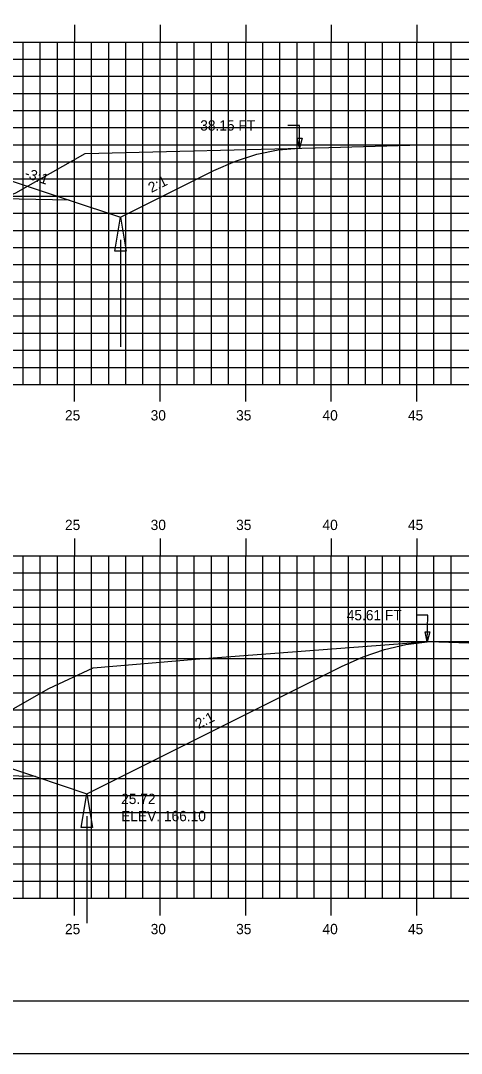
# Model space of a CAD drawing. Extents: x 1140759 to 1140929, y 608981 to 609091.
# Drawn here: x 1140863.9 to 1140889.6, y 608981.3 to 609041.6 of the extents above; entities that cross this region are included whole.
import ezdxf

# ---------------------------------------------------------------- set-up
doc = ezdxf.new("R2010")
doc.units = 0
for name, color, linetype in [('ANNOTATION', 7, 'Continuous'), ('BORDER', 7, 'Continuous'), ('D_Drainage_Ditch_Line', 7, 'Continuous'), ('D_Roadway_SlopeLines', 7, 'Continuous'), ('D_Roadway_SubGrade', 7, 'Continuous'), ('D_Text_Standard', 7, 'Continuous'), ('H_V ANNOTATION', 7, 'Continuous'), ('MAJOR', 7, 'Continuous'), ('MINOR', 7, 'Continuous'), ('PLOT BOUNDARY', 7, 'Continuous'), ('S_Roadway_Centerline', 7, 'Continuous')]:
    doc.layers.add(name, color=color, linetype=linetype)

msp = doc.modelspace()

# ---------------------------------------------------------------- linework, layer by layer
for points in [[(1140810.883, 609031.567), (1140812.133, 609031.496), (1140813.383, 609031.267), (1140814.633, 609030.879), (1140815.883, 609030.333), (1140816.276, 609030.136), (1140819.276, 609031.136), (1140827, 609033.711), (1140827.001, 609033.711), (1140831.001, 609033.871), (1140842.001, 609034.091), (1140853.001, 609033.871), (1140859.098, 609033.627), (1140866.688, 609031.097), (1140869.688, 609030.097), (1140875.149, 609032.828), (1140876.399, 609033.379), (1140877.649, 609033.781), (1140878.899, 609034.035), (1140880.149, 609034.141)], [(1140806.654, 608999.652), (1140807.904, 608999.725), (1140809.154, 608999.598), (1140810.404, 608999.272), (1140811.654, 608998.747), (1140816.276, 608996.435), (1140819.276, 608997.435), (1140827, 609000.01), (1140827.001, 609000.01), (1140831.001, 609000.17), (1140842.001, 609000.39), (1140853.001, 609000.17), (1140857.001, 609000.01), (1140864.725, 608997.435), (1140867.725, 608996.435), (1140882.606, 609003.876), (1140883.856, 609004.435), (1140885.106, 609004.861), (1140886.356, 609005.154), (1140887.606, 609005.314)]]:
    msp.add_lwpolyline(points)
at = {"layer": 'BORDER'}
msp.add_lwpolyline([(1140767.001, 608984.335), (1140927.001, 608984.335), (1140927.001, 609089.335), (1140767.001, 609089.335)], close=True, dxfattribs=at)
at = {"layer": 'D_Drainage_Ditch_Line'}
for p, q in [((1140869.688, 609028.785), (1140869.687, 609022.541)), ((1140867.725, 608995.123), (1140867.724, 608988.88))]:
    msp.add_line(p, q, dxfattribs=at)
for points in [[(1140870.016, 609028.128), (1140869.36, 609028.128), (1140869.688, 609030.097)], [(1140868.053, 608994.467), (1140867.396, 608994.467), (1140867.725, 608996.435)]]:
    msp.add_lwpolyline(points, close=True, dxfattribs=at)
at = {"layer": 'D_Roadway_SlopeLines'}
for points in [[(1140869.688, 609030.097), (1140875.149, 609032.828), (1140876.399, 609033.379), (1140877.649, 609033.781), (1140878.899, 609034.035), (1140880.149, 609034.141)], [(1140866.688, 609031.097), (1140869.688, 609030.097)], [(1140867.725, 608996.435), (1140882.606, 609003.876), (1140883.856, 609004.435), (1140885.106, 609004.861), (1140886.356, 609005.154), (1140887.606, 609005.314)], [(1140864.725, 608997.435), (1140867.725, 608996.435)]]:
    msp.add_lwpolyline(points, dxfattribs=at)
at = {"layer": 'D_Roadway_SubGrade'}
for points in [[(1140853.001, 609033.454), (1140853.001, 609033.621), (1140859.098, 609033.377), (1140859.098, 609033.627), (1140859.098, 609033.627), (1140866.688, 609031.097), (1140853.001, 609031.371)], [(1140853.001, 608999.753), (1140853.001, 608999.92), (1140857.001, 608999.76), (1140857.001, 609000.01), (1140857.001, 609000.01), (1140864.725, 608997.435), (1140853.001, 608997.67)]]:
    msp.add_lwpolyline(points, close=True, dxfattribs=at)
at = {"layer": 'D_Text_Standard'}
for points in [[(1140880.149, 609034.141), (1140880.149, 609035.465), (1140879.469, 609035.465)], [(1140887.606, 609005.304), (1140887.646, 609006.866), (1140886.966, 609006.866)]]:
    msp.add_lwpolyline(points, dxfattribs=at)
for points in [[(1140880.149, 609034.141), (1140880.004, 609034.723), (1140880.295, 609034.723)], [(1140887.606, 609005.304), (1140887.476, 609005.89), (1140887.767, 609005.882)]]:
    msp.add_lwpolyline(points, close=True, dxfattribs=at)
at = {"layer": 'MAJOR'}
for p, q in [((1140867.001, 609041.337), (1140867.001, 609040.335)), ((1140872.001, 609041.337), (1140872.001, 609040.335)), ((1140877.001, 609041.337), (1140877.001, 609040.335)), ((1140882.001, 609041.337), (1140882.001, 609040.335)), ((1140887.001, 609041.337), (1140887.001, 609040.335)), ((1140772.001, 609040.335), (1140912.001, 609040.335)), ((1140772.001, 609040.335), (1140912.001, 609040.335)), ((1140867.001, 609020.335), (1140867.001, 609040.335)), ((1140872.001, 609020.335), (1140872.001, 609040.335)), ((1140877.001, 609020.335), (1140877.001, 609040.335)), ((1140882.001, 609020.335), (1140882.001, 609040.335)), ((1140887.001, 609020.335), (1140887.001, 609040.335)), ((1140772.001, 609035.335), (1140912.001, 609035.335)), ((1140772.001, 609030.335), (1140912.001, 609030.335)), ((1140772.001, 609025.335), (1140912.001, 609025.335)), ((1140772.001, 609020.335), (1140912.001, 609020.335)), ((1140772.001, 609020.335), (1140912.001, 609020.335)), ((1140867.001, 609019.333), (1140867.001, 609020.335)), ((1140872.001, 609019.333), (1140872.001, 609020.335)), ((1140877.001, 609019.333), (1140877.001, 609020.335)), ((1140882.001, 609019.333), (1140882.001, 609020.335)), ((1140887.001, 609019.333), (1140887.001, 609020.335)), ((1140867.001, 609011.337), (1140867.001, 609010.335)), ((1140872.001, 609011.337), (1140872.001, 609010.335)), ((1140877.001, 609011.337), (1140877.001, 609010.335)), ((1140882.001, 609011.337), (1140882.001, 609010.335)), ((1140887.001, 609011.337), (1140887.001, 609010.335)), ((1140772.001, 609010.335), (1140912.001, 609010.335)), ((1140772.001, 609010.335), (1140912.001, 609010.335)), ((1140867.001, 608990.335), (1140867.001, 609010.335)), ((1140872.001, 608990.335), (1140872.001, 609010.335)), ((1140877.001, 608990.335), (1140877.001, 609010.335)), ((1140882.001, 608990.335), (1140882.001, 609010.335)), ((1140887.001, 608990.335), (1140887.001, 609010.335)), ((1140772.001, 609005.335), (1140912.001, 609005.335)), ((1140772.001, 609000.335), (1140912.001, 609000.335)), ((1140772.001, 608995.335), (1140912.001, 608995.335)), ((1140772.001, 608990.335), (1140912.001, 608990.335)), ((1140772.001, 608990.335), (1140912.001, 608990.335)), ((1140867.001, 608989.333), (1140867.001, 608990.335)), ((1140872.001, 608989.333), (1140872.001, 608990.335)), ((1140877.001, 608989.333), (1140877.001, 608990.335)), ((1140882.001, 608989.333), (1140882.001, 608990.335)), ((1140887.001, 608989.333), (1140887.001, 608990.335))]:
    msp.add_line(p, q, dxfattribs=at)
at = {"layer": 'MINOR'}
for p, q in [((1140864.001, 609020.335), (1140864.001, 609040.335)), ((1140865.001, 609020.335), (1140865.001, 609040.335)), ((1140866.001, 609020.335), (1140866.001, 609040.335)), ((1140868.001, 609020.335), (1140868.001, 609040.335)), ((1140869.001, 609020.335), (1140869.001, 609040.335)), ((1140870.001, 609020.335), (1140870.001, 609040.335)), ((1140871.001, 609020.335), (1140871.001, 609040.335)), ((1140873.001, 609020.335), (1140873.001, 609040.335)), ((1140874.001, 609020.335), (1140874.001, 609040.335)), ((1140875.001, 609020.335), (1140875.001, 609040.335)), ((1140876.001, 609020.335), (1140876.001, 609040.335)), ((1140878.001, 609020.335), (1140878.001, 609040.335)), ((1140879.001, 609020.335), (1140879.001, 609040.335)), ((1140880.001, 609020.335), (1140880.001, 609040.335)), ((1140881.001, 609020.335), (1140881.001, 609040.335)), ((1140883.001, 609020.335), (1140883.001, 609040.335)), ((1140884.001, 609020.335), (1140884.001, 609040.335)), ((1140885.001, 609020.335), (1140885.001, 609040.335)), ((1140886.001, 609020.335), (1140886.001, 609040.335)), ((1140888.001, 609020.335), (1140888.001, 609040.335)), ((1140889.001, 609020.335), (1140889.001, 609040.335)), ((1140772.001, 609039.335), (1140912.001, 609039.335)), ((1140772.001, 609038.335), (1140912.001, 609038.335)), ((1140772.001, 609037.335), (1140912.001, 609037.335)), ((1140772.001, 609036.335), (1140912.001, 609036.335)), ((1140772.001, 609034.335), (1140912.001, 609034.335)), ((1140772.001, 609033.335), (1140912.001, 609033.335)), ((1140772.001, 609032.335), (1140912.001, 609032.335)), ((1140772.001, 609031.335), (1140912.001, 609031.335)), ((1140772.001, 609029.335), (1140912.001, 609029.335)), ((1140772.001, 609028.335), (1140912.001, 609028.335)), ((1140772.001, 609027.335), (1140912.001, 609027.335)), ((1140772.001, 609026.335), (1140912.001, 609026.335)), ((1140772.001, 609024.335), (1140912.001, 609024.335)), ((1140772.001, 609023.335), (1140912.001, 609023.335)), ((1140772.001, 609022.335), (1140912.001, 609022.335)), ((1140772.001, 609021.335), (1140912.001, 609021.335)), ((1140864.001, 608990.335), (1140864.001, 609010.335)), ((1140865.001, 608990.335), (1140865.001, 609010.335)), ((1140866.001, 608990.335), (1140866.001, 609010.335)), ((1140868.001, 608990.335), (1140868.001, 609010.335)), ((1140869.001, 608990.335), (1140869.001, 609010.335)), ((1140870.001, 608990.335), (1140870.001, 609010.335)), ((1140871.001, 608990.335), (1140871.001, 609010.335)), ((1140873.001, 608990.335), (1140873.001, 609010.335)), ((1140874.001, 608990.335), (1140874.001, 609010.335)), ((1140875.001, 608990.335), (1140875.001, 609010.335)), ((1140876.001, 608990.335), (1140876.001, 609010.335)), ((1140878.001, 608990.335), (1140878.001, 609010.335)), ((1140879.001, 608990.335), (1140879.001, 609010.335)), ((1140880.001, 608990.335), (1140880.001, 609010.335)), ((1140881.001, 608990.335), (1140881.001, 609010.335)), ((1140883.001, 608990.335), (1140883.001, 609010.335)), ((1140884.001, 608990.335), (1140884.001, 609010.335)), ((1140885.001, 608990.335), (1140885.001, 609010.335)), ((1140886.001, 608990.335), (1140886.001, 609010.335)), ((1140888.001, 608990.335), (1140888.001, 609010.335)), ((1140889.001, 608990.335), (1140889.001, 609010.335)), ((1140772.001, 609009.335), (1140912.001, 609009.335)), ((1140772.001, 609008.335), (1140912.001, 609008.335)), ((1140772.001, 609007.335), (1140912.001, 609007.335)), ((1140772.001, 609006.335), (1140912.001, 609006.335)), ((1140772.001, 609004.335), (1140912.001, 609004.335)), ((1140772.001, 609003.335), (1140912.001, 609003.335)), ((1140772.001, 609002.335), (1140912.001, 609002.335)), ((1140772.001, 609001.335), (1140912.001, 609001.335)), ((1140772.001, 608999.335), (1140912.001, 608999.335)), ((1140772.001, 608998.335), (1140912.001, 608998.335)), ((1140772.001, 608997.335), (1140912.001, 608997.335)), ((1140772.001, 608996.335), (1140912.001, 608996.335)), ((1140772.001, 608994.335), (1140912.001, 608994.335)), ((1140772.001, 608993.335), (1140912.001, 608993.335)), ((1140772.001, 608992.335), (1140912.001, 608992.335)), ((1140772.001, 608991.335), (1140912.001, 608991.335))]:
    msp.add_line(p, q, dxfattribs=at)
at = {"layer": 'PLOT BOUNDARY'}
msp.add_lwpolyline([(1140758.908, 608981.276), (1140928.908, 608981.276), (1140928.908, 609091.276), (1140758.908, 609091.276)], close=True, dxfattribs=at)
at = {"layer": 'S_Roadway_Centerline'}
for points in [[(1140801.487, 609031.61), (1140807.51, 609031.545), (1140817.109, 609031.607), (1140818.751, 609031.199), (1140823.239, 609030.006), (1140825.606, 609030.431), (1140826.984, 609030.636), (1140828.295, 609030.749), (1140830.088, 609030.938), (1140836.661, 609031.15), (1140841.085, 609031.284), (1140845.133, 609031.054), (1140851.798, 609030.843), (1140853.505, 609030.727), (1140854.754, 609030.632), (1140856.271, 609030.176), (1140858.918, 609029.531), (1140863.578, 609031.533), (1140867.623, 609033.826), (1140881.853, 609034.183), (1140886.58, 609034.308), (1140902.941, 609034.493), (1140912.001, 609034.621)], [(1140801.751, 608998.976), (1140814.306, 609000.707), (1140815.787, 609000.705), (1140816.993, 609000.418), (1140823.481, 608999.018), (1140825.828, 608999.368), (1140826.874, 608999.635), (1140827.996, 608999.704), (1140830.23, 608999.898), (1140837.667, 609000.12), (1140841.075, 609000.147), (1140848.107, 608999.748), (1140851.527, 608999.693), (1140853.662, 608999.523), (1140854.647, 608999.437), (1140857.22, 608998.676), (1140858.176, 608998.42), (1140865.509, 609002.587), (1140868.086, 609003.78), (1140874.07, 609004.299), (1140887.7, 609005.321), (1140893.531, 609005.124), (1140897.997, 609004.657), (1140912.001, 609005.073)]]:
    msp.add_lwpolyline(points, dxfattribs=at)

# ---------------------------------------------------------------- texts
at = {"layer": 'ANNOTATION'}
for s, rotation, p in [('-3:1', 341.56522, (1140864.043, 609032.433)), ('2:1', 26.56505, (1140871.491, 609031.517)), ('2:1', 26.56505, (1140874.238, 609000.21))]:
    msp.add_text(s, height=0.6, rotation=rotation, dxfattribs=at).set_placement(p)
at = {"layer": 'D_Text_Standard'}
for s, p in [('38.15 FT', (1140874.346, 609035.165)), ('45.61 FT', (1140882.904, 609006.566)), ('25.72', (1140869.725, 608995.835)), ('ELEV. 166.10', (1140869.725, 608994.833))]:
    msp.add_text(s, height=0.6, dxfattribs=at).set_placement(p)
at = {"layer": 'H_V ANNOTATION'}
for s, p in [('25', (1140866.447, 609018.235)), ('30', (1140871.45, 609018.235)), ('35', (1140876.442, 609018.235)), ('40', (1140881.487, 609018.235)), ('45', (1140886.479, 609018.235)), ('25', (1140866.447, 609011.835)), ('30', (1140871.45, 609011.835)), ('35', (1140876.442, 609011.835)), ('40', (1140881.487, 609011.835)), ('45', (1140886.479, 609011.835)), ('25', (1140866.447, 608988.235)), ('30', (1140871.45, 608988.235)), ('35', (1140876.442, 608988.235)), ('40', (1140881.487, 608988.235)), ('45', (1140886.479, 608988.235))]:
    msp.add_text(s, height=0.6, dxfattribs=at).set_placement(p)

doc.saveas('drawing.dxf')
